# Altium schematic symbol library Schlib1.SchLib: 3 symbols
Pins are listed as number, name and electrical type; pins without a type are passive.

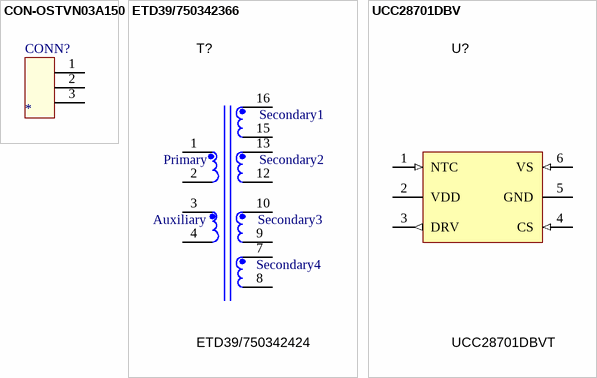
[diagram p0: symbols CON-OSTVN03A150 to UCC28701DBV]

## CON-OSTVN03A150
designator CONN?
CONN TERM BLOCK 2.54MM 3POS PCB; Manufacturer: On Shore Technology Inc; PartNumber: OSTVN03A150; SymbolCreator: x0120606; CompType: Terminal Block
footprint TB_OSTVN03A150_3P
pins: 1, 2, 3

## ETD39/750342366
designator T?, comment ETD39/750342424
Transformer,   TH; Manufacturer: wurth elektronik; SymbolCreator: a0411947; U/M: EA
footprint XFORMER_ETD39
pins: 1, 2, 3, 4, 5 hidden, 6 hidden, 7, 8, 9, 10, 11 hidden, 12, 13, 14 hidden, 15, 16

## UCC28701DBV
designator U?, comment UCC28701DBVT
IC, Constant Voltage, Constant Current PWM With Primary Side Regulation; Manufacturer: TI; SymbolCreator: a0411947; CompType: Transformer; Value: UCC2871xDBV; U/M: EA
footprint DBV-6 (Footprint not found)
pins: 1 NTC (in), 2 VDD (power), 3 DRV (out), 4 CS (in), 5 GND (power), 6 VS (in)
